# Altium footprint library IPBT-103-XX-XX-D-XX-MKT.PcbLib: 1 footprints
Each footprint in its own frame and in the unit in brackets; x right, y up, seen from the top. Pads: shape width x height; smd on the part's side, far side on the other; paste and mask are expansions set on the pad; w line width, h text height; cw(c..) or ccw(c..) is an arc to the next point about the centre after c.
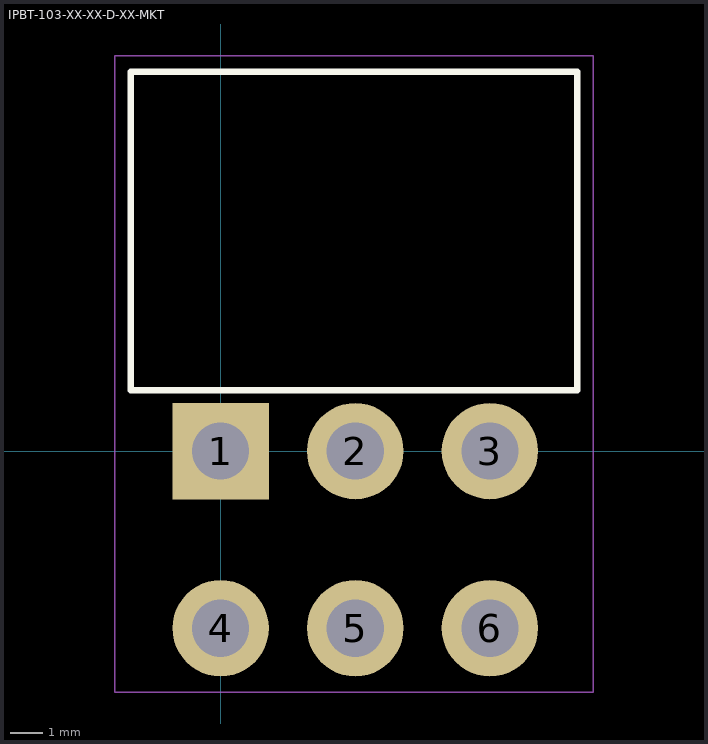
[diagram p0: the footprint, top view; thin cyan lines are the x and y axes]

## IPBT-103-XX-XX-D-XX-MKT [mm] "4.19mm pitch, 6 pin, power header; r/a"
height 10.77
pads (6):
  rect 3x3 / inner round 3 / far side rect 3x3 hole 1.78 mask+0: 1(0,0)
  round 3 hole 1.78 mask+0: 2(4.19,0) 3(8.38,0) 4(0,-5.51) 5(4.19,-5.51) 6(8.38,-5.51)
Top Overlay:
  lines w0.2: -2.8,1.9 -2.8,11.8 11.1,11.8 11.1,1.9 -2.8,1.9
Mechanical 12:
  lines w0.001: -2.8,1.9 -2.8,11.8 11.1,11.8 11.1,1.9 -2.8,1.9
Mechanical 13:
  lines w0.1: -2.8,1.9 -2.8,11.8 11.1,11.8 11.1,1.9 -2.8,1.9
  text ".Designator" at 0.254,0.254 h1.52
Mechanical 15:
  lines w0.05: -3.3,-7.5 -3.3,12.3 11.6,12.3 11.6,-7.5 -3.3,-7.5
